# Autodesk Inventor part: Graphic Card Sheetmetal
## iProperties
Created: 2005-12
Material: Default
Document SubType Name: Sheet Metal
Mass: 18.5517 g
Surface Area: 105.188 cm^2
Volume: 18.5517 cm^3
Density: 1 g/cm^3
Sheet Metal Rule: 1.0 mm
Author: Autodesk, Inc.
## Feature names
1. Extrusion1
2. Extrusion2
3. Extrusion3
4. Extrusion4
5. Extrusion5
6. Extrusion6
7. Split1
8. Extrusion7
9. Extrusion8
10. Extrusion10
11. Extrusion11
12. Extrusion12
13. Extrusion13
14. Extrusion14
15. Rectangular Pattern1
16. Extrusion16
17. Extrusion17
18. Fillet1
19. Extrusion15
20. Plate1
21. Plate2
22. Bend1
23. Plate3
24. Bend2
25. Plate4
26. Bend3
27. Cut2
28. Cut3
